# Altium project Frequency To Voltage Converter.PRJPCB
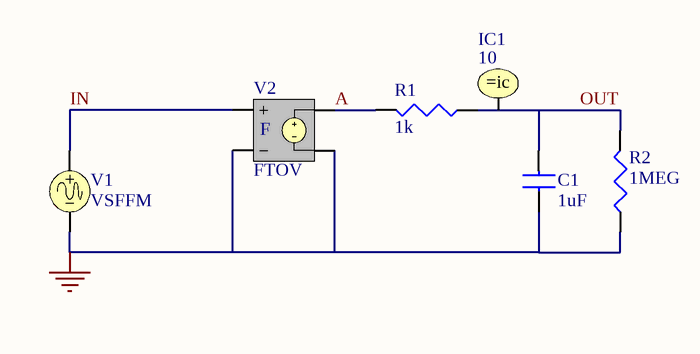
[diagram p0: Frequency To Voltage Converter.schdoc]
1 sheet, 6 parts. Net scope: global (net labels, ports and power ports of the same name join across sheets).

## Sheet Frequency To Voltage Converter.schdoc: Frequency to Voltage Converter
size A4; Organization: Altium Limited; Address1: L3, 12a Rodborough Rd; Address2: Frenchs Forest; Address3: NSW; Address4: Australia 2086; DocumentNumber: 1; SheetNumber: 1; SheetTotal: 1

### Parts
C1  1uF
IC1  10
R1  1k
R2  1MEG
V1  VSFFM
V2  FTOV

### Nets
GND: C1.2 R2.2(BOT) V1.2 V2.2(NC-) V2.4(N-)
A: R1.1(TOP) V2.3(N+)
IN: V1.1 V2.1(NC+)
OUT: C1.1 IC1.1 R1.2(BOT) R2.1(TOP)

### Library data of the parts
C1 = CAP: Capacitor
IC1 = .IC: Initial Condition
R1 R2 = RES: Resistor
V1 = VSFFM: Frequency-Modulated Sinusoidal Voltage Source
V2 = FTOV: Frequency to Voltage Converter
